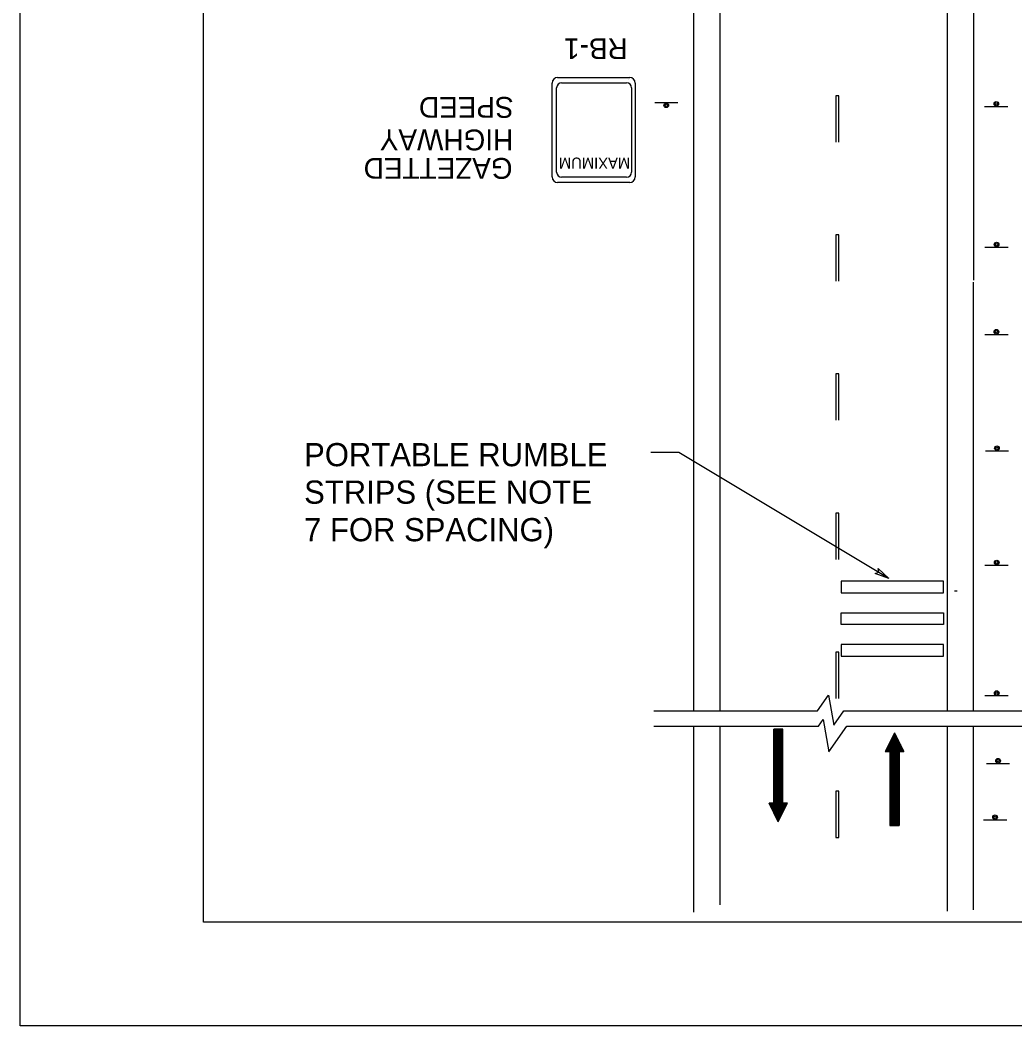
# Model space of a CAD drawing. Extents: x 1372 to 1588, y 125 to 404.
# Drawn here: x 1372.1 to 1475.8, y 125 to 229.9 of the extents above; entities that cross this region are included whole.
import ezdxf

# ---------------------------------------------------------------- set-up
doc = ezdxf.new("R2010")
doc.units = 0
for name, color, linetype in [('Level 10', 7, 'Continuous'), ('Level 2', 7, 'Continuous'), ('Level 44', 7, 'Continuous'), ('Level 5', 7, 'Continuous'), ('Level 60', 7, 'Continuous')]:
    doc.layers.add(name, color=color, linetype=linetype)

msp = doc.modelspace()

# ---------------------------------------------------------------- linework, layer by layer
at = {"layer": 'Level 10'}
for p, q in [((1445.05, 372.63), (1445.05, 157.87)), ((1468.76, 372.63), (1468.76, 157.87)), ((1471.51, 372.63), (1471.51, 202.79)), ((1442.33, 157.87), (1442.33, 334.98)), ((1471.51, 157.87), (1471.51, 202.59)), ((1468.37, 171.37), (1457.68, 171.37)), ((1457.68, 171.37), (1457.68, 170.17)), ((1468.37, 170.17), (1468.37, 171.37)), ((1457.68, 170.17), (1468.37, 170.17)), ((1469.52, 170.38), (1469.81, 170.38)), ((1469.52, 170.36), (1469.81, 170.36)), ((1457.68, 166.87), (1457.68, 168.07)), ((1457.68, 168.07), (1468.37, 168.07)), ((1468.37, 168.07), (1468.37, 166.87)), ((1468.37, 166.87), (1457.68, 166.87)), ((1468.37, 164.77), (1457.68, 164.77)), ((1457.68, 164.77), (1457.68, 163.57)), ((1468.37, 163.57), (1468.37, 164.77)), ((1457.68, 163.57), (1468.37, 163.57)), ((1442.33, 136.83), (1442.33, 156.25)), ((1445.05, 156.25), (1445.05, 137.61)), ((1450.66, 148.21), (1450.66, 155.95)), ((1451.62, 155.95), (1450.66, 155.95)), ((1450.66, 147.25), (1450.66, 155.95)), ((1450.78, 147), (1450.78, 155.95)), ((1450.9, 146.76), (1450.9, 155.95)), ((1451.02, 146.52), (1451.02, 155.95)), ((1451.14, 146.28), (1451.14, 155.95)), ((1451.26, 146.52), (1451.26, 155.95)), ((1451.38, 146.76), (1451.38, 155.95)), ((1451.5, 147), (1451.5, 155.95)), ((1451.62, 148.21), (1451.62, 155.95)), ((1451.62, 147.25), (1451.62, 155.95)), ((1463.27, 155.56), (1462.3, 153.62)), ((1463.27, 155.56), (1463.27, 145.88)), ((1463.27, 155.56), (1464.24, 153.62)), ((1468.76, 156.25), (1468.76, 136.96)), ((1471.51, 137.09), (1471.51, 156.25)), ((1462.66, 154.35), (1462.66, 153.62)), ((1462.79, 154.59), (1462.79, 145.88)), ((1462.91, 154.83), (1462.91, 145.88)), ((1463.03, 155.07), (1463.03, 145.88)), ((1463.15, 155.31), (1463.15, 145.88)), ((1463.39, 155.31), (1463.39, 145.88)), ((1463.51, 155.07), (1463.51, 145.88)), ((1463.63, 154.83), (1463.63, 145.88)), ((1463.75, 154.59), (1463.75, 145.88)), ((1463.87, 154.35), (1463.87, 153.62)), ((1462.3, 153.62), (1462.79, 153.62)), ((1462.42, 153.86), (1462.42, 153.62)), ((1462.54, 154.1), (1462.54, 153.62)), ((1462.79, 153.62), (1462.79, 145.88)), ((1463.75, 153.62), (1463.75, 145.88)), ((1463.75, 153.62), (1464.24, 153.62)), ((1464, 154.1), (1464, 153.62)), ((1464.12, 153.86), (1464.12, 153.62)), ((1451.14, 146.28), (1450.17, 148.21)), ((1450.66, 148.21), (1450.17, 148.21)), ((1450.29, 147.97), (1450.29, 148.21)), ((1450.41, 147.73), (1450.41, 148.21)), ((1450.54, 147.49), (1450.54, 148.21)), ((1451.14, 146.28), (1452.11, 148.21)), ((1452.11, 148.21), (1451.62, 148.21)), ((1451.75, 147.49), (1451.75, 148.21)), ((1451.87, 147.73), (1451.87, 148.21)), ((1451.99, 147.97), (1451.99, 148.21)), ((1462.79, 145.88), (1463.75, 145.88))]:
    msp.add_line(p, q, dxfattribs=at)
at = {"layer": 'Level 2'}
for p, q in [((1457.15, 222.03), (1457.15, 217.2)), ((1457.44, 222.03), (1457.15, 222.03)), ((1457.44, 217.2), (1457.44, 222.03)), ((1457.15, 207.52), (1457.15, 202.68)), ((1457.44, 207.52), (1457.15, 207.52)), ((1457.44, 202.68), (1457.44, 207.52)), ((1457.15, 193.01), (1457.15, 188.17)), ((1457.44, 193.01), (1457.15, 193.01)), ((1457.44, 188.17), (1457.44, 193.01)), ((1457.15, 178.49), (1457.15, 173.65)), ((1457.44, 178.49), (1457.15, 178.49)), ((1457.44, 173.65), (1457.44, 178.49)), ((1457.15, 163.98), (1457.15, 159.14)), ((1457.44, 163.98), (1457.15, 163.98)), ((1457.44, 159.14), (1457.44, 163.98)), ((1457.15, 149.46), (1457.15, 144.63)), ((1457.44, 149.46), (1457.15, 149.46)), ((1457.44, 144.63), (1457.44, 149.46)), ((1457.15, 144.63), (1457.44, 144.63))]:
    msp.add_line(p, q, dxfattribs=at)
at = {"layer": 'Level 44'}
for p, q in [((1428.12, 223.95), (1435.64, 223.95)), ((1435.5, 223.71), (1435.5, 223.71)), ((1427.54, 213.57), (1427.54, 223.37)), ((1428.02, 214.05), (1428.02, 222.87)), ((1428.54, 223.39), (1435.31, 223.39)), ((1435.83, 222.87), (1435.83, 214.05)), ((1435.83, 222.87), (1435.83, 222.87)), ((1436.22, 223.37), (1436.22, 213.57)), ((1436.22, 223.37), (1436.22, 223.37)), ((1440.66, 221.31), (1438.25, 221.31)), ((1472.66, 220.92), (1475.08, 220.92)), ((1472.66, 220.92), (1475.08, 220.92)), ((1435.31, 213.53), (1428.54, 213.53)), ((1435.64, 212.99), (1428.12, 212.99)), ((1472.69, 206.24), (1475.11, 206.24)), ((1472.68, 197.13), (1475.1, 197.13)), ((1472.74, 184.98), (1475.16, 184.98)), ((1472.7, 173.05), (1475.12, 173.05)), ((1455.23, 157.87), (1456.37, 159.49)), ((1456.37, 159.49), (1456.92, 156.37)), ((1472.7, 159.44), (1475.12, 159.44)), ((1438.14, 157.87), (1455.23, 157.87)), ((1456.92, 156.37), (1457.98, 157.87)), ((1457.98, 157.87), (1476.7, 157.87)), ((1455.32, 156.25), (1455.81, 156.95)), ((1455.81, 156.95), (1456.4, 153.59)), ((1438.14, 156.25), (1455.32, 156.25)), ((1456.4, 153.59), (1458.28, 156.25)), ((1458.28, 156.25), (1476.7, 156.25)), ((1472.85, 152.37), (1475.26, 152.37)), ((1472.54, 146.48), (1474.96, 146.48))]:
    msp.add_line(p, q, dxfattribs=at)
for centre, radius in [((1439.45, 221.04), 0.242), ((1439.45, 221.04), 0.121), ((1473.88, 221.19), 0.242), ((1473.88, 221.19), 0.242), ((1473.88, 221.19), 0.121), ((1473.88, 221.19), 0.121), ((1473.91, 206.51), 0.242), ((1473.91, 206.51), 0.121), ((1473.89, 197.41), 0.242), ((1473.89, 197.41), 0.121), ((1473.95, 185.25), 0.242), ((1473.95, 185.25), 0.121), ((1473.92, 173.32), 0.242), ((1473.92, 173.32), 0.121), ((1473.92, 159.71), 0.242), ((1473.92, 159.71), 0.121), ((1474.06, 152.64), 0.242), ((1474.06, 152.64), 0.121), ((1473.75, 146.75), 0.242), ((1473.75, 146.75), 0.121)]:
    msp.add_circle(centre, radius, dxfattribs=at)
for centre, radius, start, end in [((1428.12, 223.37), 0.58, 90, 180), ((1435.64, 223.37), 0.58, 360, 90), ((1428.54, 222.87), 0.522, 90, 180), ((1435.31, 222.87), 0.522, 360, 90), ((1428.12, 213.57), 0.58, 180, 270), ((1428.54, 214.05), 0.522, 180, 270), ((1435.31, 214.05), 0.522, 270, 360), ((1435.64, 213.57), 0.58, 270, 360)]:
    msp.add_arc(centre, radius, start, end, dxfattribs=at)
at = {"layer": 'Level 5'}
for p, q in [((1440.76, 184.82), (1437.83, 184.82)), ((1462.68, 171.67), (1440.76, 184.82))]:
    msp.add_line(p, q, dxfattribs=at)
msp.add_lwpolyline([(1462.68, 171.67), (1461.24, 172.18), (1461.61, 172.31), (1461.56, 172.71)], close=True, dxfattribs=at)
at = {"layer": 'Level 60'}
for points in [[(1372.06, 403.98), (1588.06, 403.98), (1588.06, 124.98), (1372.06, 124.98)], [(1391.18, 393.17), (1578.06, 393.17), (1578.06, 135.79), (1391.18, 135.79)]]:
    msp.add_lwpolyline(points, close=True, dxfattribs=at)

# ---------------------------------------------------------------- texts
at = {"layer": 'Level 10'}
for s, height, p in [('RB-1', 2.177, (1435.43, 228.04)), ('SPEED', 2.177, (1423.53, 221.92)), ('HIGHWAY', 2.178, (1423.49, 218.52)), ('GAZETTED', 2.177, (1423.42, 215.55))]:
    msp.add_text(s, height=height, rotation=180, dxfattribs=at).set_placement(p)
for s, p in [('PORTABLE RUMBLE', (1401.68, 183.38)), ('STRIPS (SEE NOTE', (1401.68, 179.47)), ('7 FOR SPACING)', (1401.68, 175.55))]:
    msp.add_text(s, height=2.419, dxfattribs=at).set_placement(p)
at = {"layer": 'Level 44'}
msp.add_text('MAXIMUM', height=1.15, rotation=180, dxfattribs=at).set_placement((1435.69, 215.59))

doc.saveas('drawing.dxf')
